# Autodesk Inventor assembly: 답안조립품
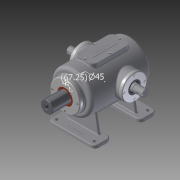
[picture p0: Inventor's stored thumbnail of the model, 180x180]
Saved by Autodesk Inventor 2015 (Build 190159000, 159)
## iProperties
Created: 2016-02
Part Number: 답안조립품
Document SubType Name: Assembly
Designer: Administrator
Author: Administrator
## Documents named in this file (15)
- C:\Users\Administrator\Desktop\360220V1012\답안조립품.iam
- C:\Users\Administrator\Desktop\360220V1012\본체.ipt
- C:\Users\Administrator\Desktop\360220V1012\슬라이드 커버.ipt
- C:\Users\Administrator\Desktop\360220V1012\볼트 M4x0.7.ipt
- C:\Users\Administrator\Desktop\360220V1012\축 커버.ipt
- C:\Users\Administrator\Desktop\360220V1012\오일실.ipt
- 오일실.ipt
- C:\Users\Administrator\Desktop\360220V1012\베어링 6205.ipt
- 베어링 6205.ipt
- C:\Users\Administrator\Desktop\360220V1012\상부커버.ipt
- C:\Users\Administrator\Desktop\360220V1012\육각머리볼트 M4.ipt
- C:\Users\Administrator\Desktop\360220V1012\부시.ipt
- C:\Users\Administrator\Desktop\360220V1012\편심축.ipt
- C:\Users\Administrator\Desktop\360220V1012\가변스프링.ipt
- C:\Users\Administrator\Desktop\360220V1012\슬라이드.ipt
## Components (13 placed, 2 different names)
1. 가변스프링:1
2. M4x0.7:1
3. M4x0.7:2
4. M4x0.7:3
5. M4x0.7:4
6. M4x0.7:5
7. M4x0.7:7
8. M4x0.7:8
9. M4x0.7:9
10. M4x0.7:6
11. M4x0.7:10
12. M4x0.7:11
13. M4x0.7:12
